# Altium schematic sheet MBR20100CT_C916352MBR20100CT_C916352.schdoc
size 127 x 101 mm
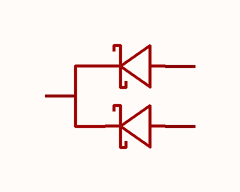
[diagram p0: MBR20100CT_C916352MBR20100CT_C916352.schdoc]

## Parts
D?  mbrf20100ct_c916352  [TO-220F-3_L10.2-W4.7-P2.54-L]  (value not drawn)

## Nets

Not connected (* = marked no-connect by the designer): D? 1(A) 2(C) 3(A)

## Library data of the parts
D? = mbrf20100ct_c916352: 二极管配置:1对共阴极;正向压降(Vf):830mV@20A;直流反向耐压(Vr):100V;整流电流:10A;; Manufacturer: JSMSEMI(杰盛微); Symbol: MBR20100CT_C916352; AddInBom: yes; ModelId: b5990cdf67854b65a85fdb5429325fb8; ModelTransform: 399.999,185.039,0,0,0,0,0,10.354,-118.11; Diode Configuration: 1对共阴极; Voltage - DC Reverse(Vr): 100V; Current - Rectified: 10A; Reverse Leakage Current (Ir): 100uA@100V; Non-Repetitive Peak Forward Surge Current: 150A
